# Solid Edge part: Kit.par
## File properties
Sűrűség: 0,000 kg/m^3
Pontosság: 0,990
Author: bmolnar
Last saved by: psaghy
Revision: 77
Username: bmolnar
Dokumentum tartalom típus: 0
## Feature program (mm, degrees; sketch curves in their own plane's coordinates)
base feature "unnamed BaseFeature 1"
sketch for "Furat_1" plane through (0, 0, 39) normal (0, 0, 1) x-axis (0, -1, 0)
  hole centre (-23.25, 23.25) bore radius 3.3235
hole "Furat_1" nominal diameter 8 finite  VBottomAngle = 118 deg; ThreadDepth = 16 mm
sketch for "unnamed Hole 1" plane through (0, 0, 39) normal (0, 0, 1) x-axis (0, -1, 0)
  hole centre (-23.25, -23.25) bore radius 3.3235
hole "unnamed Hole 1" finite
sketch for "unnamed Hole 2" plane through (0, 0, 39) normal (0, 0, 1) x-axis (0, -1, 0)
  hole centre (23.25, -23.25) bore radius 3.3235
hole "unnamed Hole 2" finite
sketch for "unnamed Hole 3" plane through (0, 0, 39) normal (0, 0, 1) x-axis (0, -1, 0)
  hole centre (23.25, 23.25) bore radius 3.3235
hole "unnamed Hole 3" finite
pattern "unnamed Pattern 1" of "Furat_1", "unnamed Hole 1", "unnamed Hole 2", "unnamed Hole 3"
sketch for "Furat_5" plane through (32.5, 0.0003, 21.2488) normal (1, 0, 0) x-axis (0, 0, -1)
hole "Furat_5" diameter 13.157 finite  ThreadDepth = 10 mm
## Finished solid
Body 1: solid body, 446 faces, 1036 edges, 651 vertices, 7 internal voids.
  Faces by surface: plane 155, cylinder 135, torus 52, cone 51, sphere 23, spline 21, swept 9
  Edges by curve: line 368, circle 356, curve on surface 286, spline 26
Bounding box of the edges (mm; curved faces can reach further): 65.000 x 65.000 x 56.500, from (-32.5, -32.5, 8) to (32.5002, 32.5, 64.5).
Cylindrical faces by radius (mm): R0.3125 x1, R0.3838 x1, R0.4089 x1, R0.4253 x1, R0.4408 x1, R0.5 x8, R0.5003 x1, R0.5483 x1, R0.5961 x1, R0.615 x1, R0.6311 x1, R0.6362 x1, R0.652 x1, R0.6792 x1, R0.73 x1, R0.7378 x1, R0.7396 x1, R0.9114 x1, R1 x20, R1.0004 x7, R1.001 x6, R1.0014 x8, R1.0015 x1, R1.0026 x1, R1.0394 x1, R1.0539 x1, R1.0734 x1, R1.0987 x1, R1.1871 x1, R1.2561 x1, R1.2722 x2, R1.3621 x1, R1.3711 x1, R1.4 x1, R1.7143 x1, R3.3235 x8, R4 x4, R4.15 x4, R4.5 x1, R5 x2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
Conical faces (half-angle, radius in mm at the cone's reference point): 0.5 deg R18.5 x4, 0.5 deg R22.25 x4, 1.6538 deg R11.75 x1, 3.5477 deg R12.7454 x1, 5.762 deg R10.4 x1, 11.1239 deg R10.0056 x1, 15 deg R18.5156 x1, 15.3654 deg R10.7214 x1, 19.3654 deg R11.1921 x1, 25.0169 deg R14.31 x1, 30 deg R5.1443 x1, 30 deg R11.8557 x2, 30 deg R12.1443 x1, 30 deg R19.5 x1, 31.4296 deg R28.625 x4, 45 deg R2.75 x1, 45 deg R2.825 x1, 45 deg R4.3 x8, 45 deg R6.35 x8, 45 deg R6.72 x1, 45 deg R10.15 x2, 45 deg R15.25 x1, 59 deg R3.3235 x4
Toroidal faces (ring radius, tube radius in mm): R0.4909 r0.5044 x1, R0.5094 r0.5004 x1, R0.8674 r0.5067 x1, R1.4976 r0.5003 x6, R4.3 r0.3 x4, R4.7 r0.3 x1, R6.45 r0.2 x4, R7.15 r0.5 x4, R9.5 r0.5 x1, R9.75 r0.5 x2, R10.3 r0.3 x1, R10.3085 r0.3 x1, R11.4279 r0.25 x1, R12.2464 r0.5 x1, R13.9897 r0.5062 x1, R14.8 r0.2 x1, R17 r2 x1, R17.6163 r0.5 x1, R19.4739 r1 x1, R19.4913 r1 x3, R20.5 r0.5 x1, R21.2587 r1 x3, R21.2761 r1 x1, R27.25 r1 x3, R31.75 r1 x6, R33.3108 r1 x1
Spherical faces by radius (mm): R0.5 x1, R1 x22
Planar faces by outward normal: +x 24, +y 9, +z 36, -x 5, -y 8, -z 24, oblique 49
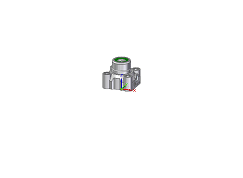
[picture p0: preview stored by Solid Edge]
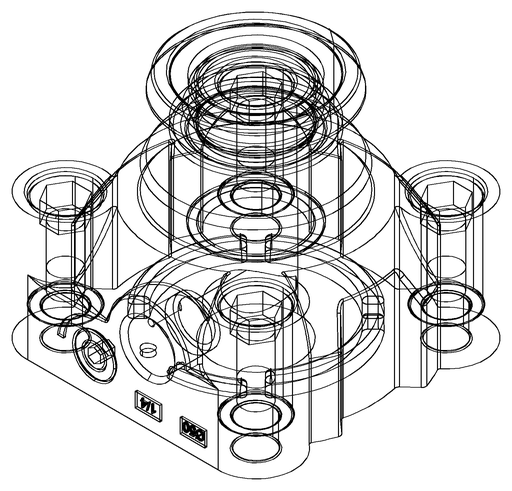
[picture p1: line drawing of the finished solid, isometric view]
